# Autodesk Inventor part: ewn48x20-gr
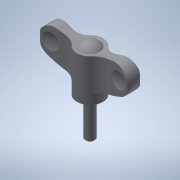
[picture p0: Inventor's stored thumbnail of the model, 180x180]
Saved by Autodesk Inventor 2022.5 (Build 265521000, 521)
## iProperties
Created: 2016-12
Part Number: ewn48x20-gr
Material: 一般
Document SubType Name: Modeling
Designer: imaocorp
Density: 1 g/cm^3
Appearance: 既定
Author: imaocorp
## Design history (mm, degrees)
node "ewn48x20-gr.x_t1"
node "ewn48x20-gr"
node "Base1"
